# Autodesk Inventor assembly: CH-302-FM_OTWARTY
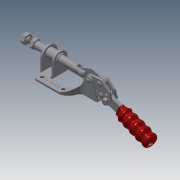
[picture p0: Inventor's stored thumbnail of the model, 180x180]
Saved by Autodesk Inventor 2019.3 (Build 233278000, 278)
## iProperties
Company: Î¢ÈíÖÐ¹ú
Created: 2013-03
Part Number: CH-302-FM_OTWARTY
Material: Ogólny
Description: STEP AP203
Document SubType Name: Assembly
Designer: CADENGINEERING4
Sending System: SolidWorks 2010
Preprocessor: SwSTEP 2.0
Title: CH-302-FM.STEP
Author: Î¢ÈíÓÃ»§
Revision Number: ÈÎºÎ
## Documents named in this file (14)
- D:\Vault_2016\Projekty\STRONA\Push-pull clamp\CH-302-FM\CH-302-FM_OTWARTY.iam
- D:\Vault_2016\Projekty\STRONA\Push-pull clamp\CH-302-FM\CH-302-FM-03 HANDLE.ipt
- D:\Vault_2016\Projekty\STRONA\Push-pull clamp\CH-302-FM\CH-302-FM-04 CONNECTING-PLATE.ipt
- D:\Vault_2016\Projekty\STRONA\Push-pull clamp\CH-302-FM\CH-302-FM-02 CREST STALK.ipt
- D:\Vault_2016\Projekty\STRONA\Push-pull clamp\CH-302-FM\CH-302-FM-09.ipt
- D:\Vault_2016\Projekty\STRONA\Push-pull clamp\CH-302-FM\M8 Nut.ipt
- D:\Vault_2016\Projekty\STRONA\Push-pull clamp\CH-302-FM\CH-302-FM-06.ipt
- D:\Vault_2016\Projekty\STRONA\Push-pull clamp\CH-302-FM\CH-302-FM-08.ipt
- D:\Vault_2016\Projekty\STRONA\Push-pull clamp\CH-302-FM\M5 Nut.ipt
- D:\Vault_2016\Projekty\STRONA\Push-pull clamp\CH-302-FM\CH-302-FM-01 BASE.ipt
- D:\Vault_2016\Projekty\STRONA\Push-pull clamp\CH-302-FM\CH-SA-052008 SPINDLE SUPPLIED.ipt
- D:\Vault_2016\Projekty\STRONA\Push-pull clamp\CH-302-FM\CH-302-FM-05 LEAD SET.ipt
- D:\Vault_2016\Projekty\STRONA\Push-pull clamp\CH-302-FM\CH-SA-085012 SPINDLE SUPPLIED.ipt
- D:\Vault_2016\Projekty\STRONA\Push-pull clamp\CH-302-FM\CH-302-F-07.ipt
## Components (17 placed, 17 different names)
1. CH-302-FM-03 HANDLE_1 — Zestawiające:1, Zestawiające:2, Zestawiające:3, Zestawiające:21, Zestawiające:22, Zestawiające:23
2. CH-302-FM-04 CONNECTING-PLATE_2 — Zestawiające:17, Zestawiające:18, Zestawiające:20, Zestawiające:35, Przejściowe:1
3. CH-302-FM-02 CREST STALK_3 — Zestawiające:6, Zestawiające:7, Zestawiające:32, Zestawiające:33, Zestawiające:34
4. CH-302-FM-09_4 — Zestawiające:1, Zestawiające:2, Zestawiające:3
5. M8 Nut_5 — Zestawiające:4, Zestawiające:5, Zestawiające:6
6. CH-302-FM-06_6 — Zestawiające:12, Zestawiające:14, Zestawiające:15, Zestawiające:17, Zestawiające:20, Zestawiające:26, Zestawiające:27, Zestawiające:28, Zestawiające:29, Zestawiające:30, Zestawiające:31
7. CH-302-FM-08_7 — Zestawiające:35, Zestawiające:36
8. CH-302-FM-08_8 — Zestawiające:26, Zestawiające:27
9. M5 Nut_9 — Równoległe:1, Zestawiające:10, Zestawiające:31
10. CH-302-FM-01 BASE_10 — Zestawiające:8, Zestawiające:9, Zestawiające:11, Zestawiające:12, Zestawiające:13, Zestawiające:14, Zestawiające:24, Zestawiające:25
11. CH-SA-052008 SPINDLE SUPPLIED_11 — Równoległe:1, Zestawiające:10, Zestawiające:30
12. CH-302-FM-05 LEAD SET_12 — Zestawiające:8, Zestawiające:9, Zestawiające:34
13. CH-302-FM-04 CONNECTING-PLATE_13 — Zestawiające:16, Zestawiające:18, Zestawiające:19, Zestawiające:32, Zestawiające:33, Zestawiające:36
14. CH-302-FM-08_14 — Zestawiające:28, Zestawiające:29
15. CH-SA-085012 SPINDLE SUPPLIED_15 — Zestawiające:4, Zestawiające:5, Zestawiające:7
16. CH-302-F-07_16 — Zestawiające:24, Zestawiające:25, Przejściowe:1
17. CH-302-FM-06_17 — Zestawiające:11, Zestawiające:13, Zestawiające:15, Zestawiające:16, Zestawiające:19, Zestawiające:21, Zestawiające:22, Zestawiające:23
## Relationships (38: Mate 36, Flush 1, Transitional 1)
- Zestawiające:1 [Mate]: CH-302-FM-03 HANDLE_1 ↔ CH-302-FM-09_4
- Zestawiające:2 [Mate]: CH-302-FM-03 HANDLE_1 ↔ CH-302-FM-09_4
- Zestawiające:3 [Mate]: CH-302-FM-03 HANDLE_1 ↔ CH-302-FM-09_4
- Zestawiające:4 [Mate]: M8 Nut_5 ↔ CH-SA-085012 SPINDLE SUPPLIED_15
- Zestawiające:5 [Mate]: M8 Nut_5 ↔ CH-SA-085012 SPINDLE SUPPLIED_15
- Zestawiające:6 [Mate]: CH-302-FM-02 CREST STALK_3 ↔ M8 Nut_5
- Zestawiające:7 [Mate]: CH-302-FM-02 CREST STALK_3 ↔ CH-SA-085012 SPINDLE SUPPLIED_15
- Zestawiające:8 [Mate]: CH-302-FM-01 BASE_10 ↔ CH-302-FM-05 LEAD SET_12
- Zestawiające:9 [Mate]: CH-302-FM-01 BASE_10 ↔ CH-302-FM-05 LEAD SET_12
- Równoległe:1 [Flush]: M5 Nut_9 ↔ CH-SA-052008 SPINDLE SUPPLIED_11
- Zestawiające:10 [Mate]: M5 Nut_9 ↔ CH-SA-052008 SPINDLE SUPPLIED_11
- Zestawiające:11 [Mate]: CH-302-FM-01 BASE_10 ↔ CH-302-FM-06_17
- Zestawiające:12 [Mate]: CH-302-FM-06_6 ↔ CH-302-FM-01 BASE_10
- Zestawiające:13 [Mate]: CH-302-FM-01 BASE_10 ↔ CH-302-FM-06_17
- Zestawiające:14 [Mate]: CH-302-FM-06_6 ↔ CH-302-FM-01 BASE_10
- Zestawiające:15 [Mate]: CH-302-FM-06_6 ↔ CH-302-FM-06_17
- Zestawiające:16 [Mate]: CH-302-FM-04 CONNECTING-PLATE_13 ↔ CH-302-FM-06_17
- Zestawiające:17 [Mate]: CH-302-FM-04 CONNECTING-PLATE_2 ↔ CH-302-FM-06_6
- Zestawiające:18 [Mate]: CH-302-FM-04 CONNECTING-PLATE_2 ↔ CH-302-FM-04 CONNECTING-PLATE_13
- Zestawiające:19 [Mate]: CH-302-FM-04 CONNECTING-PLATE_13 ↔ CH-302-FM-06_17
- Zestawiające:20 [Mate]: CH-302-FM-04 CONNECTING-PLATE_2 ↔ CH-302-FM-06_6
- Zestawiające:21 [Mate]: CH-302-FM-03 HANDLE_1 ↔ CH-302-FM-06_17
- Zestawiające:22 [Mate]: CH-302-FM-03 HANDLE_1 ↔ CH-302-FM-06_17
- Zestawiające:23 [Mate]: CH-302-FM-03 HANDLE_1 ↔ CH-302-FM-06_17
- Zestawiające:24 [Mate]: CH-302-FM-01 BASE_10 ↔ CH-302-F-07_16
- Zestawiające:25 [Mate]: CH-302-FM-01 BASE_10 ↔ CH-302-F-07_16
- Zestawiające:26 [Mate]: CH-302-FM-06_6 ↔ CH-302-FM-08_8
- Zestawiające:27 [Mate]: CH-302-FM-06_6 ↔ CH-302-FM-08_8
- Zestawiające:28 [Mate]: CH-302-FM-06_6 ↔ CH-302-FM-08_14
- Zestawiające:29 [Mate]: CH-302-FM-06_6 ↔ CH-302-FM-08_14
- Zestawiające:30 [Mate]: CH-302-FM-06_6 ↔ CH-SA-052008 SPINDLE SUPPLIED_11
- Zestawiające:31 [Mate]: CH-302-FM-06_6 ↔ M5 Nut_9
- Zestawiające:32 [Mate]: CH-302-FM-02 CREST STALK_3 ↔ CH-302-FM-04 CONNECTING-PLATE_13
- Zestawiające:33 [Mate]: CH-302-FM-02 CREST STALK_3 ↔ CH-302-FM-04 CONNECTING-PLATE_13
- Zestawiające:34 [Mate]: CH-302-FM-02 CREST STALK_3 ↔ CH-302-FM-05 LEAD SET_12
- Zestawiające:35 [Mate]: CH-302-FM-04 CONNECTING-PLATE_2 ↔ CH-302-FM-08_7
- Zestawiające:36 [Mate]: CH-302-FM-08_7 ↔ CH-302-FM-04 CONNECTING-PLATE_13
- Przejściowe:1 [Transitional]: CH-302-FM-04 CONNECTING-PLATE_2 ↔ CH-302-F-07_16
